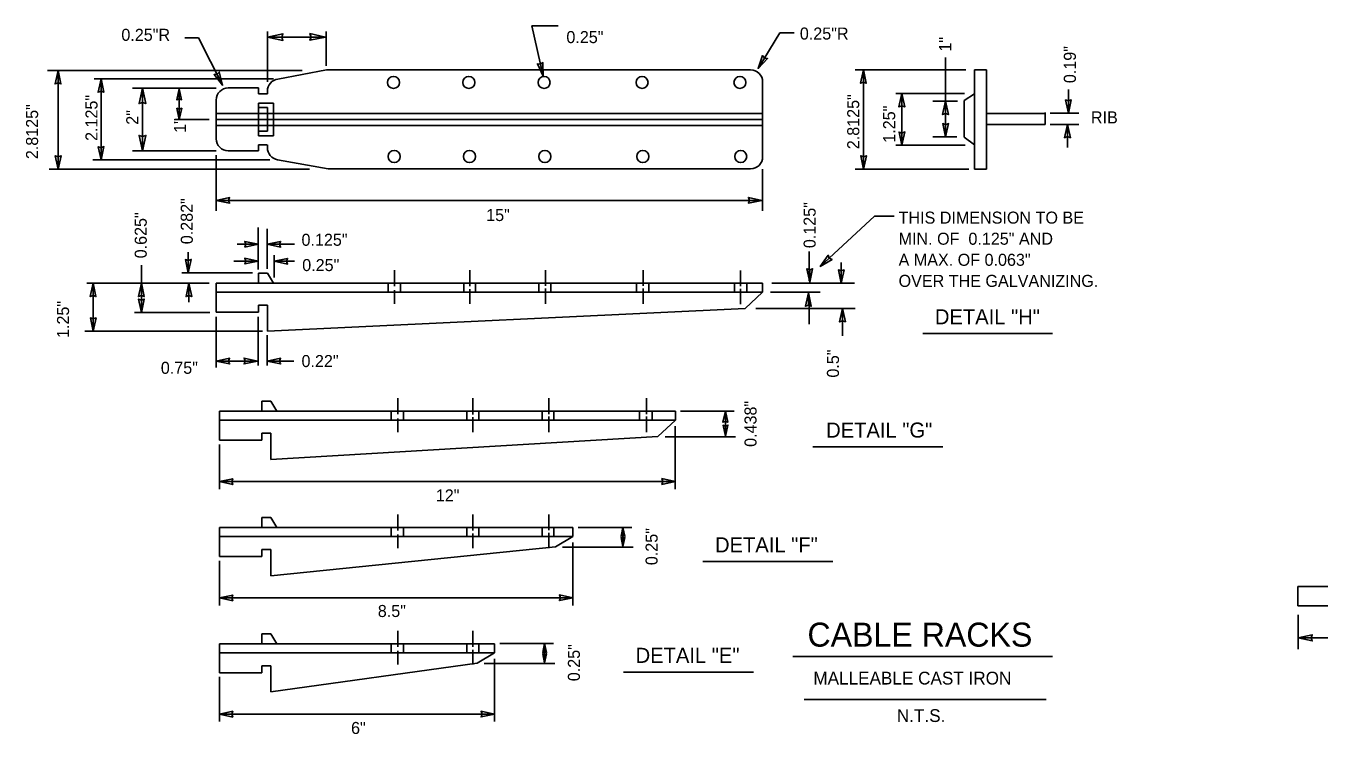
# Model space of a CAD drawing. Extents: x 19188 to 19495, y 20866 to 21061.
# Drawn here: x 19282.9 to 19367.5, y 20882 to 20928.4 of the extents above; entities that cross this region are included whole.
import ezdxf

# ---------------------------------------------------------------- set-up
doc = ezdxf.new("R2010")
doc.units = 0
doc.layers.add('G-ANNO-NOTE', color=7, linetype='Continuous')

msp = doc.modelspace()

# ---------------------------------------------------------------- linework, layer by layer
at = {"layer": 'G-ANNO-NOTE'}
for p, q in [((19317.742, 20928.352), (19316.017, 20928.352)), ((19316.017, 20928.352), (19316.756, 20925.061)), ((19293.335, 20927.575), (19294.222, 20927.575)), ((19294.222, 20927.575), (19295.798, 20924.467)), ((19298.729, 20924.695), (19298.729, 20927.986)), ((19298.729, 20927.621), (19302.522, 20927.621)), ((19298.729, 20927.621), (19299.665, 20927.621)), ((19302.522, 20927.621), (19301.585, 20927.621)), ((19302.571, 20925.746), (19302.571, 20927.986)), ((19332.247, 20927.895), (19330.819, 20925.564)), ((19333.183, 20927.895), (19332.247, 20927.895)), ((19316.756, 20925.061), (19316.581, 20925.844)), ((19330.819, 20925.564), (19331.237, 20926.248)), ((19343.086, 20926.276), (19343.086, 20921.083)), ((19300.995, 20925.426), (19284.346, 20925.426)), ((19285.036, 20925.426), (19285.036, 20918.981)), ((19285.036, 20925.426), (19285.036, 20924.624)), ((19299.123, 20924.878), (19287.4, 20924.878)), ((19287.844, 20924.878), (19287.844, 20919.575)), ((19287.844, 20924.878), (19287.844, 20924.075)), ((19295.798, 20924.467), (19295.435, 20925.182)), ((19299.41, 20924.872), (19302.582, 20925.47)), ((19330.331, 20925.47), (19302.582, 20925.47)), ((19344.416, 20925.472), (19337.175, 20925.472)), ((19337.716, 20925.472), (19337.716, 20918.981)), ((19337.716, 20925.472), (19337.716, 20924.67)), ((19344.983, 20918.981), (19344.983, 20925.472)), ((19344.983, 20925.472), (19345.771, 20925.472)), ((19345.771, 20918.981), (19345.771, 20925.472)), ((19295.38, 20924.283), (19289.912, 20924.283)), ((19290.553, 20920.169), (19290.553, 20924.283)), ((19290.553, 20924.283), (19290.553, 20923.347)), ((19292.966, 20922.232), (19292.966, 20924.238)), ((19292.966, 20924.238), (19292.966, 20923.569)), ((19296.166, 20924.288), (19298.137, 20924.288)), ((19298.137, 20924.288), (19298.137, 20923.894)), ((19298.729, 20924.091), (19298.729, 20923.894)), ((19331.12, 20919.782), (19331.12, 20924.682)), ((19351.114, 20922.638), (19351.114, 20924.192)), ((19295.378, 20923.499), (19295.378, 20920.964)), ((19298.137, 20923.894), (19298.728, 20923.894)), ((19298.137, 20923.302), (19298.137, 20921.161)), ((19298.137, 20923.302), (19299.123, 20923.302)), ((19299.123, 20923.302), (19299.123, 20921.161)), ((19344.318, 20923.918), (19339.835, 20923.918)), ((19340.229, 20923.918), (19340.229, 20920.535)), ((19340.229, 20923.918), (19340.229, 20923.115)), ((19343.874, 20923.415), (19342.249, 20923.415)), ((19343.086, 20923.415), (19343.086, 20922.613)), ((19344.983, 20923.895), (19344.292, 20923.474)), ((19344.292, 20921.074), (19344.292, 20923.474)), ((19351.114, 20922.638), (19351.114, 20923.44)), ((19292.966, 20922.232), (19292.966, 20922.901)), ((19331.12, 20922.626), (19295.355, 20922.626)), ((19298.137, 20923.007), (19298.729, 20923.007)), ((19298.729, 20923.007), (19298.729, 20921.457)), ((19345.771, 20922.626), (19349.588, 20922.626)), ((19349.588, 20921.906), (19349.588, 20922.684)), ((19349.933, 20922.638), (19351.804, 20922.638)), ((19292.671, 20922.232), (19294.912, 20922.232)), ((19331.12, 20922.232), (19295.355, 20922.232)), ((19331.12, 20921.838), (19295.355, 20921.838)), ((19298.137, 20921.457), (19298.729, 20921.457)), ((19343.086, 20921.083), (19343.086, 20921.886)), ((19345.771, 20921.906), (19349.588, 20921.906)), ((19349.933, 20921.906), (19351.804, 20921.906)), ((19351.065, 20921.906), (19351.065, 20920.398)), ((19351.065, 20921.906), (19351.065, 20921.104)), ((19290.553, 20920.169), (19290.553, 20921.105)), ((19298.137, 20921.161), (19299.123, 20921.161)), ((19340.229, 20920.535), (19340.229, 20921.337)), ((19343.825, 20921.083), (19342.249, 20921.083)), ((19344.983, 20920.557), (19344.292, 20921.074)), ((19285.036, 20918.981), (19285.036, 20919.783)), ((19287.844, 20919.575), (19287.844, 20920.377)), ((19295.38, 20920.169), (19289.912, 20920.169)), ((19295.38, 20919.895), (19295.38, 20916.248)), ((19296.166, 20920.176), (19298.137, 20920.176)), ((19298.137, 20920.57), (19298.707, 20920.57)), ((19298.137, 20920.57), (19298.137, 20920.176)), ((19298.729, 20920.373), (19298.729, 20920.57)), ((19337.716, 20918.981), (19337.716, 20919.783)), ((19344.367, 20920.535), (19339.835, 20920.535)), ((19301.487, 20918.981), (19284.444, 20918.981)), ((19298.877, 20919.575), (19287.302, 20919.575)), ((19302.708, 20918.993), (19299.386, 20919.595)), ((19302.708, 20918.993), (19330.331, 20918.993)), ((19331.114, 20918.981), (19331.114, 20916.248)), ((19344.613, 20918.981), (19337.175, 20918.981)), ((19344.983, 20918.981), (19345.771, 20918.981)), ((19295.38, 20916.934), (19331.065, 20916.934)), ((19295.38, 20916.934), (19296.182, 20916.934)), ((19331.065, 20916.934), (19330.262, 20916.934)), ((19338.428, 20915.893), (19334.891, 20912.61)), ((19339.714, 20915.893), (19338.428, 20915.893)), ((19298.123, 20912.403), (19298.123, 20915.162)), ((19298.717, 20912.446), (19298.717, 20915.077)), ((19298.123, 20914.058), (19296.751, 20914.058)), ((19298.123, 20914.058), (19297.321, 20914.058)), ((19298.717, 20914.058), (19300.501, 20914.058)), ((19298.717, 20914.058), (19299.52, 20914.058)), ((19293.551, 20912.191), (19293.55, 20913.549)), ((19293.551, 20912.191), (19293.55, 20912.994)), ((19299.175, 20911.894), (19299.175, 20913.337)), ((19334.153, 20911.67), (19334.153, 20913.58)), ((19334.891, 20912.61), (19335.48, 20913.156)), ((19290.484, 20909.603), (19290.484, 20912.7)), ((19297.757, 20912.191), (19293.139, 20912.191)), ((19298.123, 20912.955), (19296.523, 20912.955)), ((19298.123, 20912.955), (19297.321, 20912.955)), ((19298.143, 20912.176), (19298.143, 20911.545)), ((19298.143, 20912.176), (19298.731, 20912.176)), ((19298.731, 20912.176), (19299.133, 20911.516)), ((19299.175, 20912.955), (19300.501, 20912.955)), ((19299.175, 20912.955), (19299.977, 20912.955)), ((19307.036, 20912.369), (19307.036, 20911.326)), ((19311.958, 20912.369), (19311.958, 20911.313)), ((19316.92, 20912.369), (19316.92, 20911.338)), ((19323.299, 20912.369), (19323.299, 20911.338)), ((19329.677, 20912.348), (19329.677, 20911.317)), ((19334.198, 20911.582), (19334.198, 20912.384)), ((19336.257, 20911.512), (19336.257, 20912.87)), ((19336.257, 20911.512), (19336.257, 20912.315)), ((19294.922, 20911.512), (19286.921, 20911.512)), ((19287.332, 20908.371), (19287.332, 20911.512)), ((19287.332, 20911.512), (19287.332, 20910.71)), ((19290.484, 20911.512), (19290.484, 20910.71)), ((19293.596, 20911.512), (19293.596, 20910.281)), ((19293.596, 20911.512), (19293.596, 20910.71)), ((19295.38, 20911.519), (19331.114, 20911.519)), ((19295.38, 20909.621), (19295.38, 20911.519)), ((19306.618, 20910.942), (19306.618, 20911.5)), ((19307.422, 20910.942), (19307.422, 20911.525)), ((19311.566, 20910.971), (19311.566, 20911.512)), ((19312.339, 20910.942), (19312.339, 20911.512)), ((19316.483, 20910.971), (19316.483, 20911.525)), ((19317.256, 20910.971), (19317.256, 20911.525)), ((19322.859, 20910.918), (19322.859, 20911.491)), ((19323.682, 20910.918), (19323.682, 20911.512)), ((19329.284, 20910.918), (19329.284, 20911.491)), ((19330.084, 20910.918), (19330.084, 20911.491)), ((19331.114, 20911.519), (19331.114, 20910.927)), ((19331.73, 20911.512), (19337.125, 20911.512)), ((19295.38, 20910.928), (19331.114, 20910.927)), ((19307.036, 20910.159), (19307.036, 20911.052)), ((19311.958, 20910.159), (19311.958, 20911.127)), ((19316.92, 20910.159), (19316.92, 20911.165)), ((19323.299, 20910.159), (19323.299, 20911.165)), ((19329.677, 20910.138), (19329.677, 20911.143)), ((19331.114, 20910.927), (19329.969, 20909.857)), ((19331.638, 20910.918), (19334.885, 20910.918)), ((19334.112, 20910.875), (19334.112, 20910.072)), ((19334.156, 20910.654), (19334.156, 20908.829)), ((19294.968, 20909.603), (19290.027, 20909.603)), ((19290.484, 20909.603), (19290.484, 20910.404)), ((19298.143, 20909.621), (19295.38, 20909.621)), ((19298.143, 20910.08), (19298.731, 20910.08)), ((19298.143, 20910.08), (19298.143, 20909.621)), ((19298.731, 20910.08), (19298.731, 20908.366)), ((19298.731, 20908.366), (19329.969, 20909.857)), ((19330.678, 20909.857), (19337.171, 20909.857)), ((19336.348, 20909.857), (19336.348, 20908.074)), ((19336.348, 20909.857), (19336.348, 20909.054)), ((19287.332, 20908.371), (19287.332, 20909.174)), ((19295.38, 20909.305), (19295.38, 20905.995)), ((19298.123, 20909.305), (19298.123, 20906.122)), ((19298.397, 20908.371), (19286.783, 20908.371)), ((19298.717, 20908.117), (19298.717, 20906.122)), ((19341.596, 20908.216), (19350.086, 20908.216)), ((19295.38, 20906.419), (19298.077, 20906.419)), ((19295.38, 20906.419), (19296.182, 20906.419)), ((19298.077, 20906.419), (19297.275, 20906.419)), ((19298.717, 20906.419), (19300.455, 20906.419)), ((19298.717, 20906.419), (19299.52, 20906.419)), ((19298.358, 20903.791), (19298.358, 20903.159)), ((19298.358, 20903.791), (19298.945, 20903.791)), ((19298.945, 20903.791), (19299.347, 20903.13)), ((19307.251, 20903.983), (19307.251, 20902.94)), ((19312.172, 20903.983), (19312.172, 20902.928)), ((19317.135, 20903.983), (19317.135, 20902.953)), ((19323.513, 20903.983), (19323.513, 20902.953)), ((19295.594, 20903.133), (19325.416, 20903.133)), ((19295.594, 20901.236), (19295.594, 20903.133)), ((19306.832, 20902.556), (19306.832, 20903.114)), ((19307.635, 20902.556), (19307.635, 20903.139)), ((19311.78, 20902.585), (19311.78, 20903.127)), ((19312.553, 20902.556), (19312.553, 20903.127)), ((19316.698, 20902.585), (19316.698, 20903.139)), ((19317.471, 20902.585), (19317.471, 20903.139)), ((19323.074, 20902.533), (19323.074, 20903.105)), ((19323.897, 20902.533), (19323.897, 20903.127)), ((19325.416, 20903.133), (19325.416, 20902.542)), ((19325.757, 20903.142), (19329.262, 20903.142)), ((19328.685, 20903.142), (19328.685, 20901.495)), ((19328.685, 20903.142), (19328.685, 20902.473)), ((19295.594, 20902.542), (19325.416, 20902.542)), ((19307.251, 20901.773), (19307.251, 20902.667)), ((19312.172, 20901.773), (19312.172, 20902.741)), ((19317.135, 20901.773), (19317.135, 20902.779)), ((19323.513, 20901.773), (19323.513, 20902.779)), ((19325.416, 20902.542), (19324.271, 20901.472)), ((19325.402, 20902.154), (19325.402, 20898.036)), ((19328.685, 20901.495), (19328.685, 20902.164)), ((19298.358, 20901.236), (19295.594, 20901.236)), ((19298.358, 20901.695), (19298.945, 20901.695)), ((19298.358, 20901.695), (19298.358, 20901.236)), ((19298.945, 20901.695), (19298.945, 20899.98)), ((19298.945, 20899.98), (19324.271, 20901.472)), ((19324.737, 20901.454), (19329.35, 20901.454)), ((19295.59, 20900.959), (19295.59, 20898.036)), ((19334.405, 20900.8), (19342.895, 20900.8)), ((19295.59, 20898.53), (19325.402, 20898.53)), ((19295.59, 20898.53), (19296.393, 20898.53)), ((19325.402, 20898.53), (19324.6, 20898.53)), ((19298.358, 20896.183), (19298.358, 20895.551)), ((19298.358, 20896.183), (19298.945, 20896.183)), ((19298.945, 20896.183), (19299.347, 20895.523)), ((19307.251, 20896.376), (19307.251, 20895.333)), ((19312.172, 20896.376), (19312.172, 20895.32)), ((19317.135, 20896.376), (19317.135, 20895.345)), ((19295.594, 20895.526), (19318.715, 20895.526)), ((19295.594, 20893.628), (19295.594, 20895.526)), ((19306.832, 20894.948), (19306.832, 20895.506)), ((19307.635, 20894.948), (19307.635, 20895.532)), ((19311.78, 20894.977), (19311.78, 20895.519)), ((19312.553, 20894.948), (19312.553, 20895.519)), ((19316.698, 20894.977), (19316.698, 20895.532)), ((19317.471, 20894.977), (19317.471, 20895.532)), ((19318.715, 20895.526), (19318.715, 20894.934)), ((19319.056, 20895.535), (19322.561, 20895.535)), ((19321.984, 20895.535), (19321.984, 20894.281)), ((19321.984, 20895.535), (19321.984, 20895)), ((19295.594, 20894.935), (19318.715, 20894.934)), ((19307.251, 20894.166), (19307.251, 20895.059)), ((19312.172, 20894.166), (19312.172, 20895.134)), ((19317.135, 20894.166), (19317.135, 20895.172)), ((19318.715, 20894.934), (19317.571, 20894.258)), ((19318.701, 20894.546), (19318.701, 20890.429)), ((19321.984, 20894.281), (19321.984, 20894.817)), ((19298.358, 20893.628), (19295.594, 20893.628)), ((19298.358, 20894.087), (19298.945, 20894.087)), ((19298.358, 20894.087), (19298.358, 20893.628)), ((19298.945, 20892.373), (19317.571, 20894.258)), ((19298.945, 20894.087), (19298.945, 20892.373)), ((19318.036, 20894.24), (19322.65, 20894.24)), ((19295.59, 20893.352), (19295.59, 20890.429)), ((19327.214, 20893.291), (19335.704, 20893.291)), ((19366.13, 20891.66), (19366.13, 20890.404)), ((19366.13, 20891.66), (19372.975, 20891.66)), ((19295.59, 20890.923), (19318.701, 20890.923)), ((19295.59, 20890.923), (19296.393, 20890.923)), ((19318.701, 20890.923), (19317.899, 20890.923)), ((19366.13, 20890.404), (19373.394, 20890.404)), ((19366.137, 20889.803), (19366.137, 20887.563)), ((19298.358, 20888.576), (19298.358, 20887.944)), ((19298.358, 20888.576), (19298.945, 20888.576)), ((19298.945, 20888.576), (19299.347, 20887.915)), ((19307.251, 20888.768), (19307.251, 20887.725)), ((19312.172, 20888.768), (19312.172, 20887.713)), ((19295.594, 20887.918), (19313.591, 20887.918)), ((19295.594, 20886.021), (19295.594, 20887.918)), ((19306.832, 20887.341), (19306.832, 20887.899)), ((19307.635, 20887.341), (19307.635, 20887.924)), ((19311.78, 20887.37), (19311.78, 20887.912)), ((19312.553, 20887.341), (19312.553, 20887.912)), ((19313.591, 20887.918), (19313.591, 20887.327)), ((19313.932, 20887.927), (19317.436, 20887.927)), ((19316.86, 20887.927), (19316.86, 20886.674)), ((19316.86, 20887.927), (19316.86, 20887.392)), ((19366.137, 20888.31), (19375.101, 20888.31)), ((19366.137, 20888.31), (19366.99, 20888.31)), ((19295.594, 20887.328), (19313.591, 20887.327)), ((19307.251, 20886.559), (19307.251, 20887.452)), ((19312.172, 20886.559), (19312.172, 20887.526)), ((19313.591, 20887.327), (19312.446, 20886.651)), ((19313.577, 20886.939), (19313.577, 20882.821)), ((19316.86, 20886.674), (19316.86, 20887.209)), ((19333.088, 20887.091), (19350.085, 20887.091)), ((19298.358, 20886.021), (19295.594, 20886.021)), ((19298.358, 20886.48), (19298.945, 20886.48)), ((19298.358, 20886.48), (19298.358, 20886.021)), ((19298.945, 20884.765), (19312.446, 20886.651)), ((19298.945, 20886.48), (19298.945, 20884.765)), ((19312.912, 20886.633), (19317.526, 20886.633)), ((19322.021, 20886.06), (19330.511, 20886.06)), ((19295.59, 20885.745), (19295.59, 20882.821)), ((19333.825, 20884.269), (19349.662, 20884.269)), ((19295.59, 20883.315), (19313.577, 20883.315)), ((19295.59, 20883.315), (19296.393, 20883.315)), ((19313.577, 20883.315), (19312.774, 20883.315))]:
    msp.add_line(p, q, dxfattribs=at)
for points in [[(19299.665, 20927.621), (19299.747, 20927.397), (19298.729, 20927.621), (19299.745, 20927.834), (19299.665, 20927.621)], [(19301.585, 20927.621), (19301.503, 20927.845), (19302.522, 20927.621), (19301.505, 20927.407), (19301.585, 20927.621)], [(19316.581, 20925.844), (19316.752, 20925.954), (19316.756, 20925.061), (19316.387, 20925.871), (19316.581, 20925.844)], [(19331.237, 20926.248), (19331.438, 20926.208), (19330.819, 20925.564), (19331.117, 20926.402), (19331.237, 20926.248)], [(19285.036, 20924.624), (19284.844, 20924.554), (19285.036, 20925.426), (19285.219, 20924.556), (19285.036, 20924.624)], [(19287.844, 20924.075), (19287.652, 20924.005), (19287.844, 20924.878), (19288.027, 20924.007), (19287.844, 20924.075)], [(19295.435, 20925.182), (19295.575, 20925.331), (19295.798, 20924.467), (19295.241, 20925.16), (19295.435, 20925.182)], [(19337.717, 20924.669), (19337.525, 20924.599), (19337.716, 20925.472), (19337.9, 20924.601), (19337.717, 20924.669)], [(19290.553, 20923.347), (19290.329, 20923.265), (19290.553, 20924.283), (19290.767, 20923.267), (19290.553, 20923.347)], [(19292.966, 20923.569), (19292.806, 20923.51), (19292.966, 20924.238), (19293.119, 20923.512), (19292.966, 20923.569)], [(19340.229, 20923.115), (19340.037, 20923.045), (19340.229, 20923.918), (19340.412, 20923.047), (19340.229, 20923.115)], [(19343.086, 20922.612), (19342.894, 20922.542), (19343.086, 20923.415), (19343.269, 20922.544), (19343.086, 20922.612)], [(19351.114, 20923.441), (19351.306, 20923.511), (19351.114, 20922.638), (19350.931, 20923.509), (19351.114, 20923.441)], [(19292.966, 20922.901), (19293.126, 20922.959), (19292.966, 20922.232), (19292.813, 20922.958), (19292.966, 20922.901)], [(19343.086, 20921.886), (19343.277, 20921.956), (19343.086, 20921.083), (19342.902, 20921.954), (19343.086, 20921.886)], [(19351.065, 20921.103), (19350.873, 20921.033), (19351.065, 20921.906), (19351.248, 20921.035), (19351.065, 20921.103)], [(19290.553, 20921.105), (19290.777, 20921.187), (19290.553, 20920.169), (19290.339, 20921.185), (19290.553, 20921.105)], [(19340.228, 20921.337), (19340.421, 20921.407), (19340.229, 20920.535), (19340.045, 20921.406), (19340.228, 20921.337)], [(19285.036, 20919.783), (19285.228, 20919.853), (19285.036, 20918.981), (19284.853, 20919.851), (19285.036, 20919.783)], [(19287.844, 20920.377), (19288.035, 20920.448), (19287.844, 20919.575), (19287.66, 20920.446), (19287.844, 20920.377)], [(19337.716, 20919.783), (19337.908, 20919.853), (19337.716, 20918.981), (19337.533, 20919.851), (19337.716, 20919.783)], [(19296.182, 20916.934), (19296.252, 20916.742), (19295.38, 20916.934), (19296.25, 20917.118), (19296.182, 20916.934)], [(19330.262, 20916.934), (19330.192, 20917.126), (19331.065, 20916.934), (19330.193, 20916.751), (19330.262, 20916.934)], [(19297.32, 20914.058), (19297.25, 20914.25), (19298.123, 20914.058), (19297.252, 20913.875), (19297.32, 20914.058)], [(19299.52, 20914.058), (19299.59, 20913.867), (19298.717, 20914.058), (19299.588, 20914.242), (19299.52, 20914.058)], [(19293.55, 20912.994), (19293.743, 20913.064), (19293.551, 20912.191), (19293.367, 20913.062), (19293.55, 20912.994)], [(19297.32, 20912.955), (19297.25, 20913.147), (19298.123, 20912.955), (19297.252, 20912.772), (19297.32, 20912.955)], [(19299.977, 20912.955), (19300.048, 20912.763), (19299.175, 20912.955), (19300.046, 20913.138), (19299.977, 20912.955)], [(19335.48, 20913.157), (19335.662, 20913.064), (19334.891, 20912.61), (19335.405, 20913.337), (19335.48, 20913.157)], [(19334.198, 20912.384), (19334.389, 20912.455), (19334.198, 20911.582), (19334.014, 20912.453), (19334.198, 20912.384)], [(19336.256, 20912.315), (19336.448, 20912.385), (19336.257, 20911.512), (19336.073, 20912.383), (19336.256, 20912.315)], [(19287.332, 20910.71), (19287.141, 20910.639), (19287.332, 20911.512), (19287.515, 20910.641), (19287.332, 20910.71)], [(19290.484, 20910.71), (19290.292, 20910.639), (19290.484, 20911.512), (19290.667, 20910.641), (19290.484, 20910.71)], [(19293.596, 20910.71), (19293.405, 20910.639), (19293.596, 20911.512), (19293.779, 20910.641), (19293.596, 20910.71)], [(19290.484, 20910.405), (19290.676, 20910.475), (19290.484, 20909.603), (19290.301, 20910.473), (19290.484, 20910.405)], [(19334.112, 20910.072), (19333.92, 20910.002), (19334.112, 20910.875), (19334.295, 20910.004), (19334.112, 20910.072)], [(19336.348, 20909.054), (19336.156, 20908.984), (19336.348, 20909.857), (19336.531, 20908.986), (19336.348, 20909.054)], [(19287.332, 20909.174), (19287.524, 20909.244), (19287.332, 20908.371), (19287.149, 20909.243), (19287.332, 20909.174)], [(19296.182, 20906.419), (19296.253, 20906.228), (19295.38, 20906.419), (19296.25, 20906.602), (19296.182, 20906.419)], [(19297.275, 20906.419), (19297.204, 20906.611), (19298.077, 20906.419), (19297.206, 20906.236), (19297.275, 20906.419)], [(19299.52, 20906.419), (19299.59, 20906.228), (19298.717, 20906.419), (19299.588, 20906.602), (19299.52, 20906.419)], [(19328.685, 20902.473), (19328.525, 20902.415), (19328.685, 20903.142), (19328.838, 20902.417), (19328.685, 20902.473)], [(19328.685, 20902.164), (19328.845, 20902.223), (19328.685, 20901.495), (19328.532, 20902.221), (19328.685, 20902.164)], [(19296.393, 20898.53), (19296.463, 20898.339), (19295.59, 20898.53), (19296.461, 20898.713), (19296.393, 20898.53)], [(19324.6, 20898.53), (19324.529, 20898.722), (19325.402, 20898.53), (19324.531, 20898.347), (19324.6, 20898.53)], [(19321.984, 20895), (19321.856, 20894.953), (19321.984, 20895.535), (19322.107, 20894.954), (19321.984, 20895)], [(19321.984, 20894.817), (19322.112, 20894.864), (19321.984, 20894.281), (19321.862, 20894.862), (19321.984, 20894.817)], [(19296.393, 20890.923), (19296.463, 20890.731), (19295.59, 20890.923), (19296.461, 20891.106), (19296.393, 20890.923)], [(19317.899, 20890.923), (19317.828, 20891.114), (19318.701, 20890.923), (19317.831, 20890.739), (19317.899, 20890.923)], [(19366.99, 20888.31), (19367.065, 20888.106), (19366.137, 20888.31), (19367.063, 20888.505), (19366.99, 20888.31)], [(19316.86, 20887.392), (19316.732, 20887.346), (19316.86, 20887.927), (19316.982, 20887.346), (19316.86, 20887.392)], [(19316.86, 20887.21), (19316.988, 20887.256), (19316.86, 20886.674), (19316.738, 20887.255), (19316.86, 20887.21)], [(19296.393, 20883.315), (19296.463, 20883.124), (19295.59, 20883.315), (19296.461, 20883.499), (19296.393, 20883.315)], [(19312.774, 20883.315), (19312.704, 20883.507), (19313.577, 20883.315), (19312.706, 20883.132), (19312.774, 20883.315)]]:
    msp.add_lwpolyline(points, dxfattribs=at)
for centre in [(19306.972, 20924.649), (19311.899, 20924.649), (19316.826, 20924.649), (19323.231, 20924.649), (19329.636, 20924.649), (19307.021, 20919.803), (19311.948, 20919.803), (19316.875, 20919.803), (19323.28, 20919.803), (19329.686, 20919.803)]:
    msp.add_circle(centre, 0.394, dxfattribs=at)
for centre, start, end in [((19299.517, 20924.091), 97.80138, 179.99999), ((19330.331, 20924.682), 0, 90), ((19296.166, 20923.5), 90, 179.99999), ((19296.166, 20920.964), 180, 270), ((19299.517, 20920.373), 180, 260.46824), ((19330.331, 20919.782), 270, 0)]:
    msp.add_arc(centre, 0.788, start, end, dxfattribs=at)

# ---------------------------------------------------------------- texts
for s, height, p in [('0.25"R', 0.7883, (19333.552, 20927.455)), ('0.25"R', 0.7883, (19289.175, 20927.371)), ('0.25"', 0.7883, (19318.283, 20927.223)), ('RIB', 0.7883, (19352.592, 20921.969)), ('15"', 0.7883, (19313.037, 20915.58)), ('THIS DIMENSION TO BE', 0.78834, (19340.011, 20915.409)), ('0.125"', 0.7883, (19300.958, 20913.961)), ('MIN. OF  0.125" AND ', 0.78834, (19340.011, 20914.029)), ('0.25"', 0.7883, (19301.004, 20912.306)), ('A MAX. OF 0.063" ', 0.78834, (19340.011, 20912.65)), ('OVER THE GALVANIZING.', 0.78834, (19340.011, 20911.27)), ('DETAIL "H"', 0.9854, (19342.387, 20908.825)), ('0.75"', 0.7883, (19291.756, 20905.582)), ('0.22"', 0.7883, (19300.958, 20906.025)), ('DETAIL "G"', 0.9854, (19335.274, 20901.409)), ('12"', 0.7883, (19309.742, 20897.23)), ('DETAIL "F"', 0.9854, (19328.006, 20893.9)), ('8.5"', 0.7883, (19305.947, 20889.669)), ('CABLE RACKS', 1.57098, (19334.051, 20887.73)), ('DETAIL "E"', 0.9854, (19322.812, 20886.669)), ('MALLEABLE CAST IRON', 0.83785, (19334.437, 20885.252)), ('N.T.S.', 0.8379, (19339.897, 20882.799)), ('6"', 0.7883, (19304.199, 20882.015))]:
    msp.add_text(s, height=height, dxfattribs=at).set_placement(p)
for s, p in [('1"', (19343.451, 20926.665)), ('0.19"', (19351.607, 20924.603)), ('2.8125"', (19283.729, 20919.629)), ('2.125"', (19287.614, 20920.822)), ('2.8125"', (19337.438, 20920.281)), ('2"', (19290.281, 20921.88)), ('1.25"', (19339.788, 20920.705)), ('1"', (19293.41, 20921.35)), ('0.282"', (19293.847, 20914.063)), ('0.125"', (19334.587, 20913.806)), ('0.625"', (19290.834, 20913.14)), ('1.25"', (19285.753, 20907.927)), ('0.5"', (19336.112, 20905.335)), ('0.438"', (19330.72, 20900.801)), ('0.25"', (19324.249, 20893.062)), ('0.25"', (19319.168, 20885.468))]:
    msp.add_text(s, height=0.7883, rotation=90, dxfattribs=at).set_placement(p)

doc.saveas('drawing.dxf')
